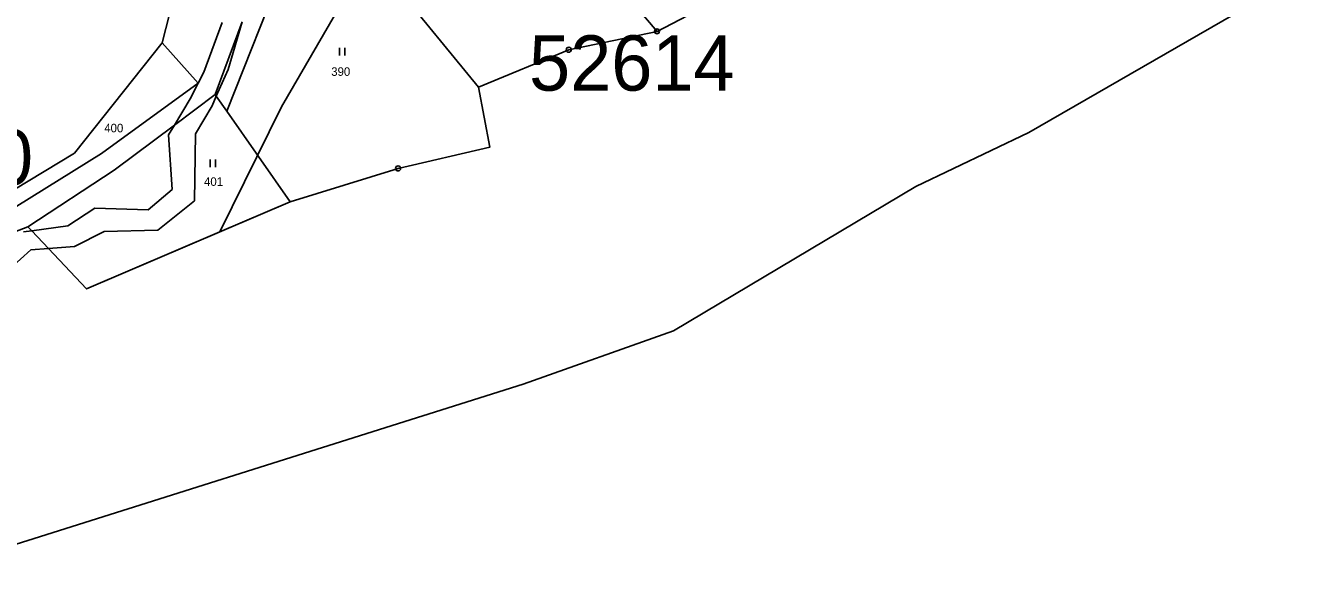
# Model space of a CAD drawing. Extents: x -725765 to -723182, y -1052705 to -1049154.
# Drawn here: x -723941.9 to -723685.7, y -1052238.6 to -1052129.8 of the extents above; entities that cross this region are included whole.
import ezdxf

# ---------------------------------------------------------------- set-up
doc = ezdxf.new("R2010")
doc.units = 0
for name, color, linetype in [('Vrstva 1', 7, 'Continuous'), ('Vrstva 13', 7, 'Continuous'), ('Vrstva 18', 7, 'Continuous'), ('Vrstva 25', 7, 'Continuous'), ('Vrstva 4', 7, 'Continuous'), ('Vrstva 52', 7, 'Continuous'), ('Vrstva 53', 7, 'Continuous')]:
    doc.layers.add(name, color=color, linetype=linetype)

msp = doc.modelspace()

# ---------------------------------------------------------------- linework, layer by layer
at = {"layer": 'Vrstva 1'}
for points in [[(-723855.94, -1052084.33), (-723816.27, -1052130.96)], [(-723816.27, -1052130.96), (-723757.29, -1052100.11)], [(-723885.09, -1052101.38), (-723851.81, -1052142.06)], [(-723914.73, -1052133.27), (-723910.43, -1052116.31)], [(-723901.9, -1052146.83), (-723890.37, -1052117.86)], [(-723906.42, -1052139.07), (-723902.77, -1052129.23)], [(-723904.2, -1052143.54), (-723898.85, -1052129.07)], [(-723833.83, -1052134.61), (-723816.27, -1052130.96)], [(-723932.21, -1052155.18), (-723914.73, -1052133.27)], [(-723914.73, -1052133.27), (-723907.55, -1052141.25)], [(-723851.81, -1052142.06), (-723833.83, -1052134.61)], [(-723926.84, -1052155.24), (-723907.55, -1052141.25)], [(-723907.55, -1052141.25), (-723906.42, -1052139.07)], [(-723912.31, -1052149.62), (-723904.2, -1052143.54)], [(-723904.2, -1052143.54), (-723903.97, -1052143.87)], [(-723903.97, -1052143.87), (-723901.9, -1052146.83)], [(-723851.81, -1052142.06), (-723849.51, -1052153.98)], [(-723901.9, -1052146.83), (-723889.27, -1052164.88)], [(-723924.28, -1052158.6), (-723912.31, -1052149.62)], [(-723867.8, -1052158.24), (-723849.51, -1052153.98)], [(-723944.23, -1052162.49), (-723932.21, -1052155.18)], [(-723943.68, -1052165.74), (-723926.84, -1052155.24)], [(-723941.45, -1052169.84), (-723924.28, -1052158.6)], [(-723889.27, -1052164.88), (-723867.8, -1052158.24)], [(-723929.79, -1052182.21), (-723889.27, -1052164.88)], [(-723961.21, -1052177.4), (-723941.45, -1052169.84)], [(-723941.45, -1052169.84), (-723940.69, -1052170.65)], [(-723940.69, -1052170.65), (-723937.37, -1052174.17)], [(-723937.37, -1052174.17), (-723929.79, -1052182.21)]]:
    msp.add_lwpolyline(points, dxfattribs=at)
at = {"layer": 'Vrstva 13'}
for points in [[(-723742.27, -1052151.08), (-723685.69, -1052118.47)], [(-723764.76, -1052161.84), (-723742.27, -1052151.08)], [(-723812.97, -1052190.53), (-723764.76, -1052161.84)], [(-723842.91, -1052201.16), (-723812.97, -1052190.53)], [(-723961.49, -1052238.61), (-723842.91, -1052201.16)]]:
    msp.add_lwpolyline(points, dxfattribs=at)
at = {"layer": 'Vrstva 25'}
for points in [[(-723879.42, -1052135.74), (-723879.42, -1052134.24)], [(-723878.38, -1052135.74), (-723878.38, -1052134.24)], [(-723905.17, -1052157.99), (-723905.17, -1052156.49)], [(-723904.13, -1052157.99), (-723904.13, -1052156.49)]]:
    msp.add_lwpolyline(points, dxfattribs=at)
for centre, radius in [((-723816.27, -1052130.96), 0.5), ((-723816.27, -1052130.96), 0.032), ((-723833.83, -1052134.61), 0.5), ((-723833.83, -1052134.61), 0.032), ((-723867.8, -1052158.24), 0.5), ((-723867.8, -1052158.24), 0.032)]:
    msp.add_circle(centre, radius, dxfattribs=at)
at = {"layer": 'Vrstva 4'}
for points in [[(-723901.62, -1052138.54), (-723898.85, -1052129.07)], [(-723903.97, -1052143.87), (-723901.62, -1052138.54)], [(-723909.18, -1052144.4), (-723907.55, -1052141.25)], [(-723904.8, -1052145.77), (-723903.97, -1052143.87)], [(-723912.31, -1052149.62), (-723909.18, -1052144.4)], [(-723908.12, -1052151.36), (-723904.8, -1052145.77)], [(-723913.48, -1052151.58), (-723912.31, -1052149.62)], [(-723913.48, -1052151.58), (-723912.76, -1052162.43)], [(-723908.27, -1052164.67), (-723908.12, -1052151.36)], [(-723917.55, -1052166.47), (-723912.76, -1052162.43)], [(-723933.48, -1052169.69), (-723928.13, -1052166.12)], [(-723928.13, -1052166.12), (-723917.55, -1052166.47)], [(-723915.62, -1052170.54), (-723908.27, -1052164.67)], [(-723940.69, -1052170.65), (-723933.48, -1052169.69)], [(-723942.31, -1052170.86), (-723940.69, -1052170.65)], [(-723932.19, -1052173.76), (-723926.26, -1052170.81)], [(-723926.26, -1052170.81), (-723915.62, -1052170.54)], [(-723949.16, -1052181.88), (-723940.85, -1052174.44)], [(-723940.85, -1052174.44), (-723937.37, -1052174.17)], [(-723937.37, -1052174.17), (-723932.19, -1052173.76)]]:
    msp.add_lwpolyline(points, dxfattribs=at)
at = {"layer": 'Vrstva 52'}
for points in [[(-724102.57, -1052226.97), (-724094.97, -1052220.93), (-724086.67, -1052217.06), (-724083.68, -1052216.19), (-724059.51, -1052209.19), (-724048.17, -1052219.4), (-724039.36, -1052217.61), (-724044.72, -1052211.91), (-724026.1, -1052206.3), (-724009.71, -1052194.73), (-724004.89, -1052192.09), (-723992.25, -1052185.16), (-723964.25, -1052171.44), (-723946.29, -1052163.74), (-723944.23, -1052162.49), (-723932.21, -1052155.18), (-723914.73, -1052133.27), (-723910.43, -1052116.31), (-723910.94, -1052080), (-723910.23, -1052078.98)], [(-723903.23, -1052170.85), (-723889.27, -1052164.88), (-723867.8, -1052158.24), (-723849.51, -1052153.98), (-723851.81, -1052142.06), (-723833.83, -1052134.61), (-723816.27, -1052130.96), (-723757.29, -1052100.11), (-723726.26, -1052089.34)], [(-723903.23, -1052170.85), (-723890.98, -1052145.98), (-723873.08, -1052115.04), (-723866.75, -1052107.59), (-723849.6, -1052098.27), (-723818.29, -1052090.07), (-723772.44, -1052089.69), (-723726.26, -1052089.34)], [(-723898.85, -1052129.07), (-723904.2, -1052143.54), (-723912.31, -1052149.62), (-723924.28, -1052158.6), (-723941.45, -1052169.84), (-723940.69, -1052170.65), (-723937.37, -1052174.17), (-723929.79, -1052182.21), (-723903.23, -1052170.85)]]:
    msp.add_lwpolyline(points, dxfattribs=at)

# ---------------------------------------------------------------- texts
at = {"layer": 'Vrstva 18'}
for s, p in [('390', (-723881.1, -1052139.82)), ('400', (-723926.26, -1052151.05)), ('401', (-723906.41, -1052161.71))]:
    msp.add_text(s, height=1.7, dxfattribs=at).set_placement(p)
at = {"layer": 'Vrstva 53'}
for s, p in [('52614', (-723841.74, -1052142.76)), ('55800', (-723981.32, -1052161.53))]:
    msp.add_text(s, height=11, dxfattribs=at).set_placement(p)

doc.saveas('drawing.dxf')
